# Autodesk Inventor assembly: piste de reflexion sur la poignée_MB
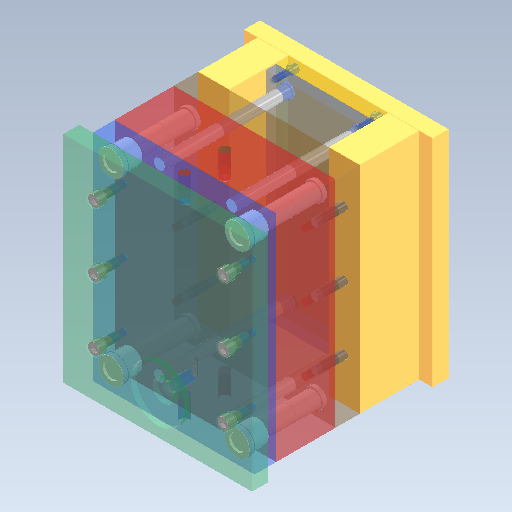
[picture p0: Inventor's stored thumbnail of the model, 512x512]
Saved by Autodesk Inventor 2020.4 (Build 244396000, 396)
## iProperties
Created: 2021-10
Part Number: piste de reflexion sur la poignée_MB
Document SubType Name: Assembly
Designer: mel
Author: mel
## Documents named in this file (16)
- D:\travail\année 2020-2021\itec\prépa injection plastique eduscol\dossier de travail\Ensemble des pièces de l'activité\Conception de moule2\Mo\FUTABA_SA-S 1\piste de reflexion sur la poignée_MB.iam
- C:\Users\mel\Documents\Inventor\Content Center Files\R2020\fr-FR\JIS 1176\JIS 1176 M10x30.ipt
- C:\Users\mel\Documents\Inventor\Content Center Files\R2020\fr-FR\GBA\M-GBA 30x39.ipt
- D:\travail\année 2020-2021\itec\prépa injection plastique eduscol\dossier de travail\Ensemble des pièces de l'activité\Conception de moule2\Mo\FUTABA_SA-S 1\piste de reflexion sur la poignée_MB_SA-SB1.ipt
- D:\travail\année 2020-2021\itec\prépa injection plastique eduscol\dossier de travail\Ensemble des pièces de l'activité\Conception de moule2\Mo\FUTABA_SA-S 1\piste de reflexion sur la poignée_MB_SA-SB2.ipt
- D:\travail\année 2020-2021\itec\prépa injection plastique eduscol\dossier de travail\Ensemble des pièces de l'activité\Conception de moule2\Mo\FUTABA_SA-S 1\piste de reflexion sur la poignée_MB_SA-EP.ipt
- C:\Users\mel\Documents\Inventor\Content Center Files\R2020\fr-FR\GPA\M-GPA30x147x69.ipt
- D:\travail\année 2020-2021\itec\prépa injection plastique eduscol\dossier de travail\Ensemble des pièces de l'activité\Conception de moule2\Mo\FUTABA_SA-S 1\piste de reflexion sur la poignée_MB_SA-ERP.ipt
- D:\travail\année 2020-2021\itec\prépa injection plastique eduscol\dossier de travail\Ensemble des pièces de l'activité\Conception de moule2\Mo\FUTABA_SA-S 1\piste de reflexion sur la poignée_MB_SA-BCP.ipt
- C:\Users\mel\Documents\Inventor\Content Center Files\R2020\fr-FR\JIS 1176\JIS 1176 M14x30.ipt
- D:\travail\année 2020-2021\itec\prépa injection plastique eduscol\dossier de travail\Ensemble des pièces de l'activité\Conception de moule2\Mo\FUTABA_SA-S 1\piste de reflexion sur la poignée_MB_RPN.ipt
- D:\travail\année 2020-2021\itec\prépa injection plastique eduscol\dossier de travail\Ensemble des pièces de l'activité\Conception de moule2\Mo\FUTABA_SA-S 1\piste de reflexion sur la poignée_MB_SA-S-AP.ipt
- D:\travail\année 2020-2021\itec\prépa injection plastique eduscol\dossier de travail\Ensemble des pièces de l'activité\Conception de moule2\Mo\FUTABA_SA-S 1\piste de reflexion sur la poignée_MB_SA-S-BP.ipt
- D:\travail\année 2020-2021\itec\prépa injection plastique eduscol\dossier de travail\Ensemble des pièces de l'activité\Conception de moule2\Mo\FUTABA_SA-S 1\piste de reflexion sur la poignée_MB_SA-TCP.ipt
- D:\travail\année 2020-2021\itec\prépa injection plastique eduscol\dossier de travail\Ensemble des pièces de l'activité\Conception de moule2\Mo\FUTABA_SA-S 1\piste de reflexion sur la poignée_MB_SA-SP.ipt
- C:\Users\mel\Documents\Inventor\Content Center Files\R2020\fr-FR\JIS 1176\JIS 1176 M14x180.ipt
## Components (37 placed, 15 different names)
1. piste de reflexion sur la poignée_MB_SA-SB1:1 — Affleurement:1, Affleurement:3, Placage:1, Placage:5
2. piste de reflexion sur la poignée_MB_SA-SB2:2 — Affleurement:2, Affleurement:4, Placage:2, Placage:6
3. piste de reflexion sur la poignée_MB_SA-EP:1 — Logement:1, Affleurement:5, Affleurement:6, Ejection, Placage:4
4. piste de reflexion sur la poignée_MB_SA-ERP:1 — Logement:7, Affleurement:7, Affleurement:8, Placage:4
5. piste de reflexion sur la poignée_MB_SA-BCP:1 — Logement:8, Ejection, Affleurement:9, Affleurement:10, Placage:5, Placage:6
6. piste de reflexion sur la poignée_MB_SA-S-AP:1 — Logement:2, Logement:5, Affleurement:11, Affleurement:12, Placage:7, PL1, Affleurement:19
7. piste de reflexion sur la poignée_MB_SA-S-BP:1 — Logement:3, Logement:4, Affleurement:13, Affleurement:14, PL1, Placage:9
8. piste de reflexion sur la poignée_MB_SA-TCP:1 — Logement:6, Placage:7, Affleurement:15, Affleurement:16
9. piste de reflexion sur la poignée_MB_SA-SP:1 — Placage:1, Placage:2, Affleurement:17, Affleurement:18, Placage:9
10. GPA 30x147x69:1 — Logement:3
11. GPA 30x147x69:3
12. JIS 1176 M14x30:1 — Logement:6
13. JIS 1176 M14x30:2
14. JIS 1176 M14x30:3
15. JIS 1176 M14x30:4
16. JIS 1176 M14x30:5
17. JIS 1176 M14x30:6
18. JIS 1176 M10x30:1 — Logement:1
19. JIS 1176 M10x30:2
20. JIS 1176 M10x30:3
21. JIS 1176 M10x30:4
22. JIS 1176 M14x180:1 — Logement:8
23. JIS 1176 M14x180:2
24. JIS 1176 M14x180:3
25. JIS 1176 M14x180:4
26. JIS 1176 M14x180:5
27. JIS 1176 M14x180:6
28. GBA 30x39:1 — Logement:2
29. GBA 30x39:3
30. GPA 30x147x69:2 — Logement:4
31. GPA 30x147x69:4
32. piste de reflexion sur la poignée_MB_RPN:1 — Logement:7
33. piste de reflexion sur la poignée_MB_RPN:2
34. piste de reflexion sur la poignée_MB_RPN:3
35. piste de reflexion sur la poignée_MB_RPN:4
36. GBA 30x39:2 — Logement:5
37. GBA 30x39:4
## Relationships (36: Flush 19, Mate 9, Insert 8)
- Logement:1 [Insert]: piste de reflexion sur la poignée_MB_SA-EP:1 ↔ JIS 1176 M10x30:1
- Logement:2 [Insert]: piste de reflexion sur la poignée_MB_SA-S-AP:1 ↔ GBA 30x39:1
- Logement:3 [Insert]: piste de reflexion sur la poignée_MB_SA-S-BP:1 ↔ GPA 30x147x69:1
- Logement:4 [Insert]: piste de reflexion sur la poignée_MB_SA-S-BP:1 ↔ GPA 30x147x69:2
- Logement:5 [Insert]: piste de reflexion sur la poignée_MB_SA-S-AP:1 ↔ GBA 30x39:2
- Logement:6 [Insert]: piste de reflexion sur la poignée_MB_SA-TCP:1 ↔ JIS 1176 M14x30:1
- Logement:7 [Insert]: piste de reflexion sur la poignée_MB_SA-ERP:1 ↔ piste de reflexion sur la poignée_MB_RPN:1
- Logement:8 [Insert]: piste de reflexion sur la poignée_MB_SA-BCP:1 ↔ JIS 1176 M14x180:1
- Affleurement:1 [Flush]: piste de reflexion sur la poignée_MB_SA-SB1:1
- Affleurement:2 [Flush]: piste de reflexion sur la poignée_MB_SA-SB2:2
- Affleurement:3 [Flush]: piste de reflexion sur la poignée_MB_SA-SB1:1
- Affleurement:4 [Flush]: piste de reflexion sur la poignée_MB_SA-SB2:2
- Placage:1 [Mate]: piste de reflexion sur la poignée_MB_SA-SB1:1 ↔ piste de reflexion sur la poignée_MB_SA-SP:1
- Placage:2 [Mate]: piste de reflexion sur la poignée_MB_SA-SB2:2 ↔ piste de reflexion sur la poignée_MB_SA-SP:1
- Affleurement:5 [Flush]: piste de reflexion sur la poignée_MB_SA-EP:1
- Affleurement:6 [Flush]: piste de reflexion sur la poignée_MB_SA-EP:1
- Ejection [Mate]: piste de reflexion sur la poignée_MB_SA-EP:1 ↔ piste de reflexion sur la poignée_MB_SA-BCP:1
- Affleurement:7 [Flush]: piste de reflexion sur la poignée_MB_SA-ERP:1
- Affleurement:8 [Flush]: piste de reflexion sur la poignée_MB_SA-ERP:1
- Placage:4 [Mate]: piste de reflexion sur la poignée_MB_SA-EP:1 ↔ piste de reflexion sur la poignée_MB_SA-ERP:1
- Affleurement:9 [Flush]: piste de reflexion sur la poignée_MB_SA-BCP:1
- Affleurement:10 [Flush]: piste de reflexion sur la poignée_MB_SA-BCP:1
- Placage:5 [Mate]: piste de reflexion sur la poignée_MB_SA-SB1:1 ↔ piste de reflexion sur la poignée_MB_SA-BCP:1
- Placage:6 [Mate]: piste de reflexion sur la poignée_MB_SA-SB2:2 ↔ piste de reflexion sur la poignée_MB_SA-BCP:1
- Affleurement:11 [Flush]: piste de reflexion sur la poignée_MB_SA-S-AP:1
- Affleurement:12 [Flush]: piste de reflexion sur la poignée_MB_SA-S-AP:1
- Placage:7 [Mate]: piste de reflexion sur la poignée_MB_SA-S-AP:1 ↔ piste de reflexion sur la poignée_MB_SA-TCP:1
- Affleurement:13 [Flush]: piste de reflexion sur la poignée_MB_SA-S-BP:1
- Affleurement:14 [Flush]: piste de reflexion sur la poignée_MB_SA-S-BP:1
- PL1 [Mate]: piste de reflexion sur la poignée_MB_SA-S-AP:1 ↔ piste de reflexion sur la poignée_MB_SA-S-BP:1
- Affleurement:15 [Flush]: piste de reflexion sur la poignée_MB_SA-TCP:1
- Affleurement:16 [Flush]: piste de reflexion sur la poignée_MB_SA-TCP:1
- Affleurement:17 [Flush]: piste de reflexion sur la poignée_MB_SA-SP:1
- Affleurement:18 [Flush]: piste de reflexion sur la poignée_MB_SA-SP:1
- Placage:9 [Mate]: piste de reflexion sur la poignée_MB_SA-S-BP:1 ↔ piste de reflexion sur la poignée_MB_SA-SP:1
- Affleurement:19 [Flush]: piste de reflexion sur la poignée_MB_SA-S-AP:1
